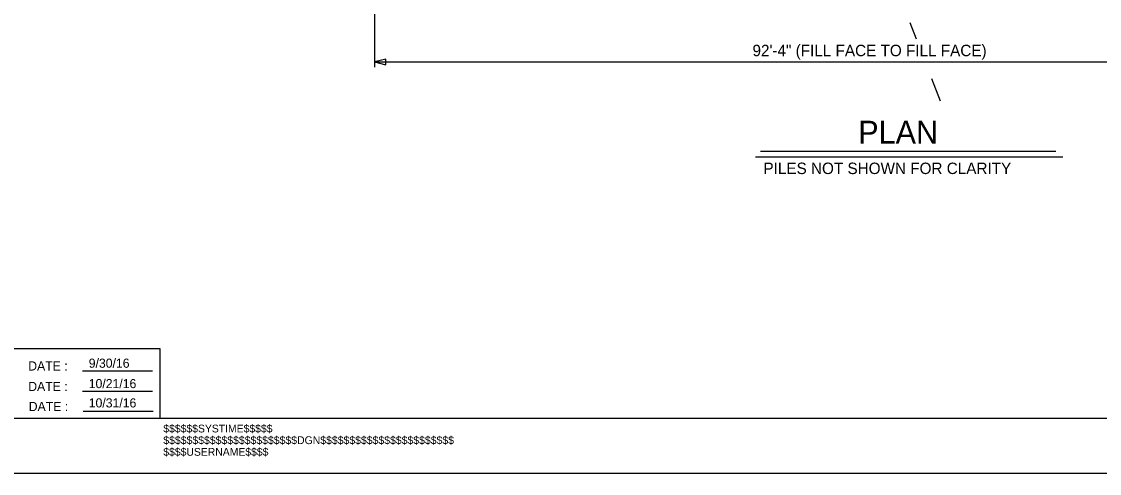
# Model space of a CAD drawing. Extents: x 471 to 2034, y -623 to 126.
# Drawn here: x 609.9 to 704.3, y -92.8 to -53.3 of the extents above; entities that cross this region are included whole.
import ezdxf

# ---------------------------------------------------------------- set-up
doc = ezdxf.new("R2010")
doc.units = 0
for name, color, linetype in [('Auto Dimensioning', 7, 'Continuous'), ('Exist Hydro Stream or Body of Water', 7, 'Continuous'), ('Plan Sheet CELL', 7, 'Continuous'), ('Plot Label CELL', 7, 'Continuous'), ('Plot Shape CELL', 7, 'Continuous'), ('Sub End Bent Cap Lines CELL', 7, 'Continuous'), ('Subtitle Text', 7, 'Continuous'), ('Text', 7, 'Continuous'), ('Title Text', 7, 'Continuous')]:
    doc.layers.add(name, color=color, linetype=linetype)

# ---------------------------------------------------------------- blocks, each defined once
blk = doc.blocks.new('AH')
at = {"layer": 'Sub End Bent Cap Lines CELL'}
blk.add_lwpolyline([(0, 0), (-1.25, 0.31), (-1.25, -0.31)], close=True, dxfattribs=at)

msp = doc.modelspace()

# ---------------------------------------------------------------- linework, layer by layer
at = {"layer": 'Auto Dimensioning'}
for p, q in [((640.824, -28.265), (640.824, -57.285)), ((640.824, -56.82), (733.154, -56.82))]:
    msp.add_line(p, q, dxfattribs=at)
at = {"layer": 'Exist Hydro Stream or Body of Water'}
for points in [[(688.277, -54.829), (687.729, -53.414)], [(690.381, -60.262), (689.62, -58.299)]]:
    msp.add_lwpolyline(points, dxfattribs=at)
at = {"layer": 'Plan Sheet CELL'}
for p, q in [((575.848, -81.884), (622.039, -81.884)), ((622.039, -81.884), (622.039, -87.977)), ((615.268, -83.862), (621.387, -83.862)), ((615.268, -85.618), (621.387, -85.618)), ((615.312, -87.373), (621.431, -87.373)), ((615.312, -87.373), (621.431, -87.373)), ((575.848, -87.977), (831.85, -87.977))]:
    msp.add_line(p, q, dxfattribs=at)
at = {"layer": 'Plot Shape CELL'}
msp.add_lwpolyline([(567.415, 83.173), (831.92, 83.173), (831.92, -92.826), (567.415, -92.826)], close=True, dxfattribs=at)
at = {"layer": 'Title Text'}
for p, q in [((674.616, -64.632), (700.458, -64.632)), ((674.167, -65.132), (701.076, -65.132))]:
    msp.add_line(p, q, dxfattribs=at)

# ---------------------------------------------------------------- block references
at = {"layer": 'Auto Dimensioning', "xscale": 0.8, "yscale": 0.8000000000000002, "rotation": 180}
msp.add_blockref('AH', (640.824, -56.82), dxfattribs=at)

# ---------------------------------------------------------------- texts
at = {"layer": 'Plan Sheet CELL'}
for p in [(610.507, -83.822), (610.507, -85.613), (610.551, -87.368)]:
    msp.add_text('DATE :', height=0.8, dxfattribs=at).set_placement(p)
at = {"layer": 'Plot Label CELL'}
for s, height, p in [('$$$$$$SYSTIME$$$$$', 0.68029, (622.331, -89.24)), ('$$$$$$$$$$$$$$$$$$$$$$$DGN$$$$$$$$$$$$$$$$$$$$$$$', 0.68446, (622.331, -90.26)), ('$$$$USERNAME$$$$', 0.68029, (622.331, -91.28))]:
    msp.add_text(s, height=height, dxfattribs=at).set_placement(p)
at = {"layer": 'Subtitle Text'}
for s, p in [('9/30/16', (615.804, -83.58)), ('10/21/16', (615.804, -85.366)), ('10/31/16', (615.804, -87.054))]:
    msp.add_text(s, height=0.8, dxfattribs=at).set_placement(p)
at = {"layer": 'Text'}
for s, p in [('92\'-4" (FILL FACE TO FILL FACE)', (673.916, -56.32)), ('PILES NOT SHOWN FOR CLARITY', (674.873, -66.632))]:
    msp.add_text(s, height=1, dxfattribs=at).set_placement(p)
at = {"layer": 'Title Text'}
msp.add_text('PLAN', height=2, dxfattribs=at).set_placement((683.175, -63.969))

doc.saveas('drawing.dxf')
